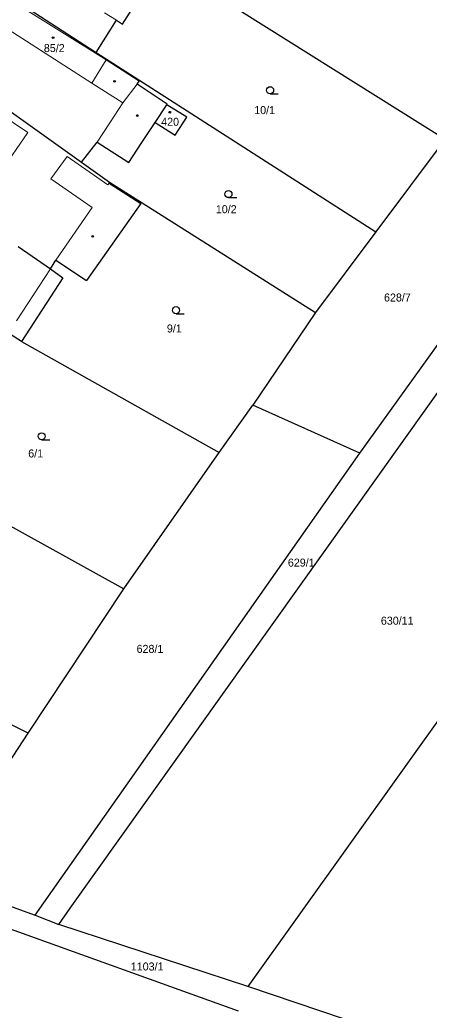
# Model space of a CAD drawing. Extents: x -694609 to -690140, y -1033292 to -1029794.
# Drawn here: x -692438.9 to -692351.9, y -1031915.8 to -1031705.3 of the extents above; entities that cross this region are included whole.
import ezdxf
from ezdxf.enums import TextEntityAlignment as Align

# ---------------------------------------------------------------- set-up
doc = ezdxf.new("R2010")
doc.units = 0
doc.header["$LTSCALE"] = 0.68
for name, color, linetype, lineweight in [('1', 7, 'Continuous', 25), ('3', 7, 'Continuous', 25), ('4', 7, 'Continuous', 13), ('5', 7, 'Continuous', 25)]:
    doc.layers.add(name, color=color, linetype=linetype, lineweight=lineweight)
doc.layers.add('2', color=7, linetype='Continuous')

msp = doc.modelspace()

# ---------------------------------------------------------------- linework, layer by layer
at = {"layer": '1'}
for p, q in [((-692410, -1031692.14), (-692348.49, -1031730.69)), ((-692440.5, -1031700.65), (-692422.66, -1031712.29)), ((-692417.06, -1031706.27), (-692413.08, -1031699.93)), ((-692422.66, -1031712.29), (-692418.37, -1031705.46)), ((-692418.37, -1031705.46), (-692417.06, -1031706.27)), ((-692422.66, -1031712.29), (-692413.64, -1031718.08)), ((-692451.98, -1031716.89), (-692425.76, -1031735.6)), ((-692413.97, -1031719.05), (-692413.51, -1031718.37)), ((-692407.59, -1031723.29), (-692413.97, -1031719.05)), ((-692413.51, -1031718.37), (-692413.64, -1031718.08)), ((-692413.64, -1031718.08), (-692363.26, -1031750.4)), ((-692410.13, -1031727.15), (-692407.66, -1031723.39)), ((-692407.66, -1031723.39), (-692407.59, -1031723.29)), ((-692403.41, -1031726.07), (-692407.66, -1031723.39)), ((-692405.88, -1031729.85), (-692403.41, -1031726.07)), ((-692413.08, -1031731.65), (-692410.13, -1031727.15)), ((-692410.13, -1031727.15), (-692405.88, -1031729.85)), ((-692425.76, -1031735.6), (-692422.43, -1031731.34)), ((-692422.43, -1031731.34), (-692415.77, -1031735.7)), ((-692415.77, -1031735.7), (-692413.08, -1031731.65)), ((-692348.49, -1031730.69), (-692363.26, -1031750.4)), ((-692425.76, -1031735.6), (-692419.82, -1031739.83)), ((-692419.94, -1031740.03), (-692419.82, -1031739.83)), ((-692419.94, -1031740.03), (-692413.19, -1031744.39)), ((-692419.82, -1031739.83), (-692376.08, -1031767.55)), ((-692413.19, -1031744.39), (-692424.72, -1031760.75)), ((-692366.63, -1031797.44), (-692329.14, -1031745.08)), ((-692428.17, -1031894.13), (-692324.48, -1031748.55)), ((-692363.26, -1031750.4), (-692376.08, -1031767.55)), ((-692439.26, -1031753.5), (-692432.4, -1031758.29)), ((-692432.4, -1031758.29), (-692431.28, -1031756.44)), ((-692431.28, -1031756.44), (-692424.72, -1031760.75)), ((-692432.4, -1031758.29), (-692429.79, -1031760.16)), ((-692429.79, -1031760.16), (-692438.54, -1031773.68)), ((-692438.54, -1031773.68), (-692452.67, -1031764.84)), ((-692376.08, -1031767.55), (-692389.39, -1031787.22)), ((-692438.54, -1031773.68), (-692396.51, -1031797.31)), ((-692396.51, -1031797.31), (-692389.39, -1031787.22)), ((-692366.63, -1031797.44), (-692389.39, -1031787.22)), ((-692435.67, -1031895.57), (-692366.63, -1031797.44)), ((-692416.83, -1031826.23), (-692396.51, -1031797.31)), ((-692463.48, -1031800.46), (-692416.83, -1031826.23)), ((-692321.02, -1031813.52), (-692390.46, -1031910.76)), ((-692437.1, -1031856.91), (-692416.83, -1031826.23)), ((-692437.1, -1031856.91), (-692490.54, -1031830.78)), ((-692392.4, -1031916.03), (-692552.44, -1031858.36)), ((-692457.39, -1031887.7), (-692437.1, -1031856.91)), ((-692457.39, -1031887.7), (-692435.67, -1031895.57)), ((-692430.61, -1031897.59), (-692428.17, -1031894.13)), ((-692435.67, -1031895.57), (-692430.61, -1031897.59)), ((-692390.46, -1031910.76), (-692430.61, -1031897.59)), ((-692369.91, -1031917.67), (-692390.46, -1031910.76))]:
    msp.add_line(p, q, dxfattribs=at)
at = {"layer": '3'}
for p, q in [((-692385.723, -1031721.06), (-692383.973, -1031721.06)), ((-692394.573, -1031743.14), (-692392.823, -1031743.14)), ((-692405.713, -1031767.8), (-692403.963, -1031767.8)), ((-692434.263, -1031794.59), (-692432.513, -1031794.59))]:
    msp.add_line(p, q, dxfattribs=at)
for centre in [(-692385.7229, -1031720.3098), (-692394.5729, -1031742.3898), (-692405.7129, -1031767.0498), (-692434.2629, -1031793.8398)]:
    msp.add_circle(centre, 0.75, dxfattribs=at)
at = {"layer": '4'}
for p, q in [((-692420.54, -1031713.84), (-692439.38, -1031702.08)), ((-692420.87, -1031703.88), (-692418.37, -1031705.46)), ((-692442.42, -1031706.71), (-692423.59, -1031718.8)), ((-692423.59, -1031718.8), (-692420.54, -1031713.84)), ((-692420.54, -1031713.84), (-692413.51, -1031718.37)), ((-692423.59, -1031718.8), (-692417.01, -1031722.99)), ((-692417.01, -1031722.99), (-692413.97, -1031719.05)), ((-692437.23, -1031729.27), (-692447.21, -1031722.56)), ((-692419.76, -1031727.23), (-692417.01, -1031722.99)), ((-692422.43, -1031731.34), (-692419.76, -1031727.23)), ((-692437.23, -1031729.27), (-692442.92, -1031737.68)), ((-692423.54, -1031745.25), (-692431.28, -1031756.44)), ((-692432.4, -1031758.29), (-692439.6, -1031769.3))]:
    msp.add_line(p, q, dxfattribs=at)
for points in [[(-692428.84, -1031734.42), (-692432.28, -1031739.17), (-692423.54, -1031745.25)], [(-692419.94, -1031740.03), (-692420.19, -1031740.39), (-692428.84, -1031734.42)]]:
    msp.add_lwpolyline(points, dxfattribs=at)
at = {"layer": '5'}
for centre in [(-692431.8168, -1031709.1392), (-692418.7768, -1031718.4392), (-692413.9468, -1031725.6892), (-692407.0368, -1031724.9892), (-692423.4068, -1031751.3692)]:
    msp.add_circle(centre, 0.175, dxfattribs=at)

# ---------------------------------------------------------------- texts
at = {"layer": '2'}
for s, p in [('85/2', (-692431.579, -1031712.205)), ('10/1', (-692386.879, -1031725.385)), ('420', (-692406.969, -1031727.865)), ('10/2', (-692395.039, -1031746.445)), ('628/7', (-692358.67, -1031765.205)), ('9/1', (-692406.07, -1031771.785)), ('6/1', (-692435.53, -1031798.345)), ('629/1', (-692379.1, -1031821.535)), ('630/11', (-692358.71, -1031833.875)), ('628/1', (-692411.24, -1031839.865)), ('1103/1', (-692411.84, -1031907.355))]:
    msp.add_text(s, height=1.7, dxfattribs=at).set_placement(p, align=Align.CENTER)

doc.saveas('drawing.dxf')
